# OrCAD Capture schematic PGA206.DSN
size B; title: PGA206, High-Speed Programmable Gain INSTRUMENTATION- AMP; rev: 1.0; note: Datasheet: SBOS033
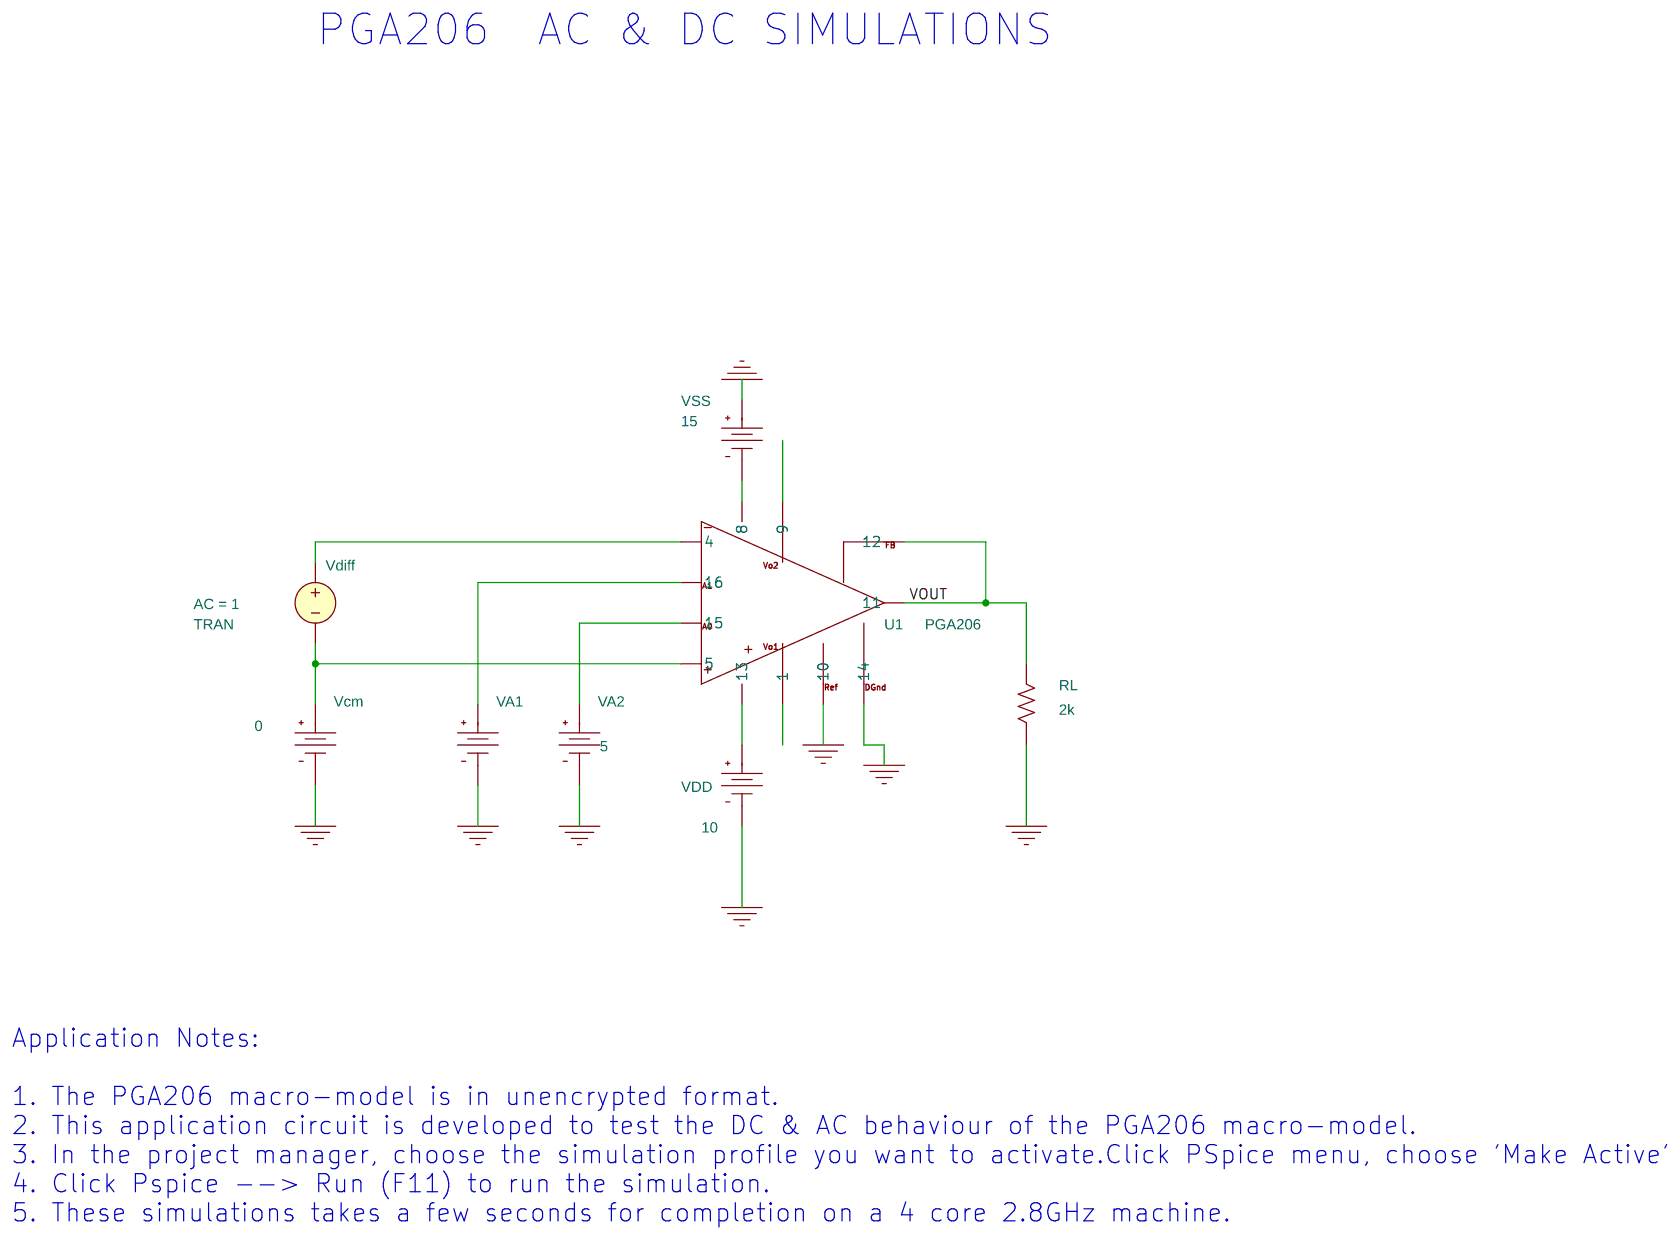
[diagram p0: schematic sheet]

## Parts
RL  2k  [AX/RC05]
U1  PGA206
VA1  VDC
VA2  VDC
Vcm  VDC
VDD  VDC
Vdiff  VSRC
VSS  VDC

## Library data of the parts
RL = R
U1 = PGA206
VA1 = VDC
VA2 = VDC: DC: 5
Vcm = VDC: DC: 0
VDD = VDC: DC: 10
Vdiff = VSRC: AC: 1; DC: 0; TRAN: PWL TIME_SCALE_FACTOR=100U VALUE_SCALE_FACTOR=1 REPEAT FOREVER(0, 0) (100U 1) (499.9M 1) (500.1M -1) (999.9M -1) (1,0) ENDREPEAT
VSS = VDC: DC: 15

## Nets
0: RL.1 U1.10 U1.14 VA1.1(-) VA2.1(-) Vcm.1(-) VDD.1(-) VSS.0(+)
VOUT: RL.2 U1.11 U1.12
N00753: U1.4 Vdiff.0(+)
N14306469: U1.13 VDD.0(+)
N14306729: U1.8 VSS.1(-)
N14306823: U1.15 VA2.0(+)
N14306892: U1.16 VA1.0(+)
N14307635: U1.5 Vcm.0(+) Vdiff.1(-)

Not connected (* = marked no-connect by the designer): U1 1 9

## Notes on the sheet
- PGA206  AC & DC SIMULATIONS
- Application Notes:
  1. The PGA206 macro-model is in unencrypted format.
  2. This application circuit is developed to test the DC & AC behaviour of the PGA206 macro-model.
  3. In the project manager, choose the simulation profile you want to activate.Click PSpice menu, choose 'Make Active'
  4. Click Pspice --> Run (F11) to run the simulation.
  5. These simulations takes a few seconds for completion on a 4 core 2.8GHz machine.
